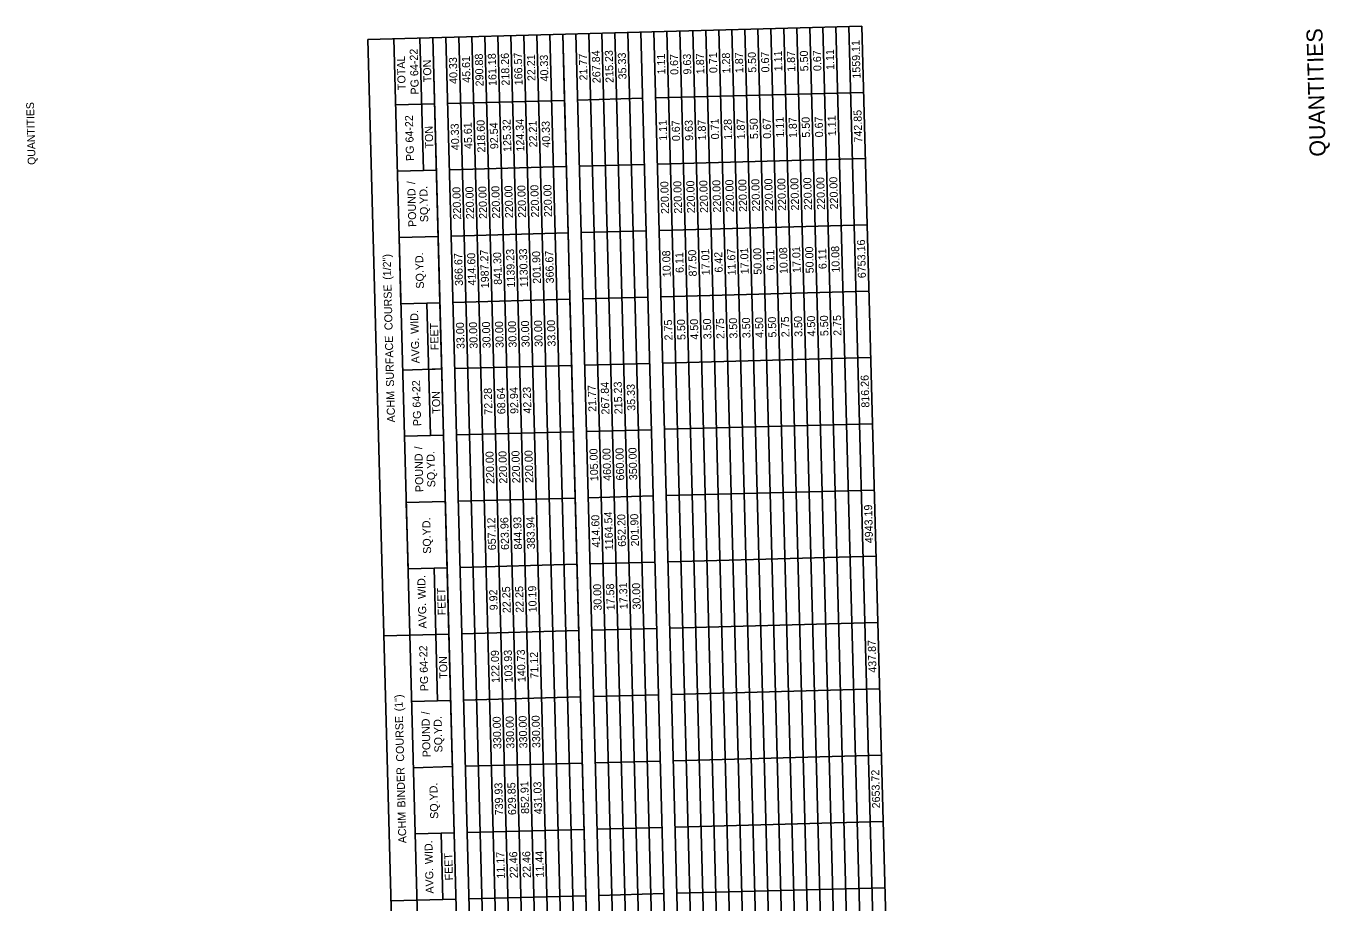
# Model space of a CAD drawing. Extents: x 1930078 to 1931323, y 596452 to 607874.
# Drawn here: x 1930161 to 1931139, y 604738 to 605396 of the extents above; entities that cross this region are included whole.
import ezdxf

# ---------------------------------------------------------------- set-up
doc = ezdxf.new("R2010")
doc.units = 0
for name, color, linetype in [('Default', 7, 'Continuous'), ('R_Border', 7, 'Continuous'), ('R_Border Prem', 7, 'Continuous')]:
    doc.layers.add(name, color=color, linetype=linetype)

msp = doc.modelspace()

# ---------------------------------------------------------------- linework, layer by layer
at = {"layer": 'Default'}
for p, q in [((1930787.82, 605395.91), (1930417.45, 605385.97)), ((1930787.82, 605395.91), (1930417.45, 605385.97)), ((1930564.98, 605340.19), (1930563.65, 605389.9)), ((1930603.34, 603911.35), (1930563.65, 605389.9)), ((1930613.09, 603911.62), (1930573.4, 605390.16)), ((1930622.83, 603911.88), (1930583.14, 605390.42)), ((1930632.58, 603912.14), (1930592.89, 605390.68)), ((1930642.33, 603912.4), (1930602.64, 605390.94)), ((1930652.07, 603912.66), (1930612.38, 605391.21)), ((1930661.82, 603912.92), (1930622.13, 605391.47)), ((1930661.82, 603912.92), (1930622.13, 605391.47)), ((1930671.57, 603913.19), (1930631.88, 605391.73)), ((1930681.31, 603913.45), (1930641.62, 605391.99)), ((1930691.06, 603913.71), (1930651.37, 605392.25)), ((1930700.81, 603913.97), (1930661.12, 605392.51)), ((1930710.55, 603914.23), (1930670.86, 605392.78)), ((1930720.3, 603914.49), (1930680.61, 605393.04)), ((1930730.04, 603914.76), (1930690.35, 605393.3)), ((1930739.79, 603915.02), (1930700.1, 605393.56)), ((1930749.54, 603915.28), (1930709.85, 605393.82)), ((1930759.28, 603915.54), (1930719.59, 605394.08)), ((1930769.03, 603915.8), (1930729.34, 605394.35)), ((1930778.78, 603916.06), (1930739.09, 605394.61)), ((1930788.52, 603916.33), (1930748.83, 605394.87)), ((1930798.27, 603916.59), (1930758.58, 605395.13)), ((1930808.02, 603916.85), (1930768.33, 605395.39)), ((1930817.76, 603917.11), (1930778.07, 605395.65)), ((1930827.51, 603917.37), (1930787.82, 605395.91)), ((1930457.14, 603907.43), (1930417.45, 605385.97)), ((1930466.3, 604292.94), (1930436.95, 605386.5)), ((1930459.11, 605287.61), (1930456.44, 605387.02)), ((1930505.88, 603908.74), (1930466.19, 605387.28)), ((1930471.52, 605188.45), (1930466.19, 605387.28)), ((1930515.62, 603909), (1930475.93, 605387.54)), ((1930525.37, 603909.26), (1930485.68, 605387.8)), ((1930535.12, 603909.52), (1930495.42, 605388.07)), ((1930544.86, 603909.79), (1930505.17, 605388.33)), ((1930554.61, 603910.05), (1930514.92, 605388.59)), ((1930564.35, 603910.31), (1930524.66, 605388.85)), ((1930574.1, 603910.57), (1930534.41, 605389.11)), ((1930583.85, 603910.83), (1930544.16, 605389.37)), ((1930593.59, 603911.09), (1930553.9, 605389.64)), ((1930623.46, 605341.76), (1930574.73, 605340.45)), ((1930623.46, 605341.76), (1930574.73, 605340.45)), ((1930789.15, 605346.21), (1930633.21, 605342.02)), ((1930789.15, 605346.21), (1930633.21, 605342.02)), ((1930467.52, 605337.57), (1930438.28, 605336.79)), ((1930564.98, 605340.19), (1930477.27, 605337.84)), ((1930564.98, 605340.19), (1930477.27, 605337.84)), ((1930567.65, 605240.78), (1930564.98, 605340.19)), ((1930790.49, 605296.5), (1930634.54, 605292.31)), ((1930790.49, 605296.5), (1930634.54, 605292.31)), ((1930468.85, 605287.87), (1930439.61, 605287.08)), ((1930566.32, 605290.48), (1930478.6, 605288.13)), ((1930566.32, 605290.48), (1930478.6, 605288.13)), ((1930624.8, 605292.05), (1930576.07, 605290.74)), ((1930624.8, 605292.05), (1930576.07, 605290.74)), ((1930791.82, 605246.79), (1930635.88, 605242.61)), ((1930791.82, 605246.79), (1930635.88, 605242.61)), ((1930470.19, 605238.16), (1930440.95, 605237.37)), ((1930442.28, 605187.67), (1930440.95, 605237.37)), ((1930567.65, 605240.78), (1930479.93, 605238.42)), ((1930567.65, 605240.78), (1930479.93, 605238.42)), ((1930568.99, 605191.07), (1930567.65, 605240.78)), ((1930626.13, 605242.35), (1930577.4, 605241.04)), ((1930626.13, 605242.35), (1930577.4, 605241.04)), ((1930793.16, 605197.09), (1930637.21, 605192.9)), ((1930793.16, 605197.09), (1930637.21, 605192.9)), ((1930471.52, 605188.45), (1930442.28, 605187.67)), ((1930471.52, 605188.45), (1930461.78, 605188.19)), ((1930464.45, 605088.78), (1930461.78, 605188.19)), ((1930476.86, 604989.62), (1930471.52, 605188.45)), ((1930568.99, 605191.07), (1930481.27, 605188.71)), ((1930568.99, 605191.07), (1930481.27, 605188.71)), ((1930581, 604743.71), (1930568.99, 605191.07)), ((1930627.47, 605192.64), (1930578.73, 605191.33)), ((1930627.47, 605192.64), (1930578.73, 605191.33)), ((1930794.49, 605147.38), (1930638.55, 605143.19)), ((1930794.49, 605147.38), (1930638.55, 605143.19)), ((1930472.86, 605138.75), (1930443.62, 605137.96)), ((1930472.86, 605138.75), (1930463.11, 605138.48)), ((1930570.32, 605141.36), (1930482.6, 605139.01)), ((1930570.32, 605141.36), (1930482.6, 605139.01)), ((1930628.8, 605142.93), (1930580.07, 605141.62)), ((1930628.8, 605142.93), (1930580.07, 605141.62)), ((1930795.83, 605097.67), (1930639.88, 605093.49)), ((1930795.83, 605097.67), (1930639.88, 605093.49)), ((1930474.19, 605089.04), (1930444.95, 605088.25)), ((1930571.66, 605091.65), (1930483.94, 605089.3)), ((1930571.66, 605091.65), (1930483.94, 605089.3)), ((1930630.14, 605093.22), (1930581.4, 605091.92)), ((1930630.14, 605093.22), (1930581.4, 605091.92)), ((1930797.16, 605047.97), (1930641.22, 605043.78)), ((1930797.16, 605047.97), (1930641.22, 605043.78)), ((1930475.53, 605039.33), (1930446.29, 605038.55)), ((1930447.62, 604988.84), (1930446.29, 605038.55)), ((1930572.99, 605041.95), (1930485.27, 605039.59)), ((1930572.99, 605041.95), (1930485.27, 605039.59)), ((1930631.47, 605043.52), (1930582.74, 605042.21)), ((1930631.47, 605043.52), (1930582.74, 605042.21)), ((1930476.86, 604989.62), (1930447.62, 604988.84)), ((1930476.86, 604989.62), (1930467.11, 604989.36)), ((1930469.78, 604889.95), (1930467.11, 604989.36)), ((1930482.2, 604790.8), (1930476.86, 604989.62)), ((1930574.33, 604992.24), (1930486.61, 604989.89)), ((1930574.33, 604992.24), (1930486.61, 604989.89)), ((1930632.8, 604993.81), (1930584.07, 604992.5)), ((1930632.8, 604993.81), (1930584.07, 604992.5)), ((1930798.49, 604998.26), (1930642.55, 604994.07)), ((1930798.49, 604998.26), (1930642.55, 604994.07)), ((1930575.66, 604942.53), (1930487.94, 604940.18)), ((1930575.66, 604942.53), (1930487.94, 604940.18)), ((1930634.14, 604944.1), (1930585.41, 604942.8)), ((1930634.14, 604944.1), (1930585.41, 604942.8)), ((1930799.83, 604948.55), (1930643.88, 604944.36)), ((1930799.83, 604948.55), (1930643.88, 604944.36)), ((1930478.19, 604939.92), (1930429.46, 604938.61)), ((1930448.96, 604939.13), (1930429.46, 604938.61)), ((1930478.19, 604939.92), (1930468.45, 604939.66)), ((1930576.99, 604892.83), (1930489.28, 604890.47)), ((1930576.99, 604892.83), (1930489.28, 604890.47)), ((1930635.47, 604894.4), (1930586.74, 604893.09)), ((1930635.47, 604894.4), (1930586.74, 604893.09)), ((1930801.16, 604898.84), (1930645.22, 604894.66)), ((1930801.16, 604898.84), (1930645.22, 604894.66)), ((1930479.53, 604890.21), (1930450.29, 604889.43)), ((1930578.33, 604843.12), (1930490.61, 604840.76)), ((1930578.33, 604843.12), (1930490.61, 604840.76)), ((1930636.81, 604844.69), (1930588.07, 604843.38)), ((1930636.81, 604844.69), (1930588.07, 604843.38)), ((1930802.5, 604849.14), (1930646.55, 604844.95)), ((1930802.5, 604849.14), (1930646.55, 604844.95)), ((1930480.86, 604840.5), (1930451.62, 604839.72)), ((1930638.14, 604794.98), (1930589.41, 604793.67)), ((1930638.14, 604794.98), (1930589.41, 604793.67)), ((1930803.83, 604799.43), (1930647.89, 604795.24)), ((1930803.83, 604799.43), (1930647.89, 604795.24)), ((1930482.2, 604790.8), (1930452.96, 604790.01)), ((1930482.2, 604790.8), (1930472.45, 604790.53)), ((1930473.79, 604740.83), (1930472.45, 604790.53)), ((1930486.2, 604641.67), (1930482.2, 604790.8)), ((1930579.66, 604793.41), (1930491.94, 604791.06)), ((1930579.66, 604793.41), (1930491.94, 604791.06)), ((1930639.48, 604745.27), (1930590.74, 604743.97)), ((1930639.48, 604745.27), (1930590.74, 604743.97)), ((1930805.17, 604749.72), (1930649.22, 604745.54)), ((1930805.17, 604749.72), (1930649.22, 604745.54)), ((1930483.53, 604741.09), (1930434.8, 604739.78)), ((1930581, 604743.71), (1930493.28, 604741.35)), ((1930581, 604743.71), (1930493.28, 604741.35)), ((1930585, 604594.58), (1930581, 604743.71))]:
    msp.add_line(p, q, dxfattribs=at)

# ---------------------------------------------------------------- texts
for s, p in [('1559.11', (1930787, 605356.55)), ('TOTAL', (1930445.86, 605348.01)), (' 64-22', (1930455.39, 605356.25)), ('40.33', (1930484.75, 605352.61)), ('45.61', (1930494.48, 605353.45)), ('290.88', (1930504.3, 605350.8)), ('161.18', (1930514.05, 605351.06)), ('218.26', (1930523.8, 605351.33)), ('166.57', (1930533.54, 605351.59)), ('22.21', (1930543.21, 605354.76)), ('40.33', (1930552.97, 605354.44)), ('21.77', (1930582.21, 605355.23)), ('267.84', (1930592.02, 605353.17)), ('215.23', (1930601.77, 605353.42)), ('35.33', (1930611.45, 605356.01)), ('1.11', (1930640.61, 605359.71)), ('0.67', (1930650.38, 605359.39)), ('9.63', (1930660.12, 605359.65)), ('1.87', (1930669.87, 605359.91)), ('0.71', (1930679.6, 605360.75)), ('1.28', (1930689.36, 605360.43)), ('1.87', (1930699.11, 605360.7)), ('5.50', (1930708.85, 605360.97)), ('0.67', (1930718.6, 605361.22)), ('1.11', (1930728.33, 605362.06)), ('1.87', (1930738.09, 605361.74)), ('5.50', (1930747.84, 605362.01)), ('0.67', (1930757.59, 605362.26)), ('1.11', (1930767.32, 605363.11)), ('TON', (1930465.21, 605353.87)), ('PG', (1930455.7, 605344.65)), ('742.85', (1930788.29, 605308.62)), (' 64-22', (1930451.85, 605306.41)), ('40.33', (1930486.08, 605302.9)), ('45.61', (1930495.81, 605303.75)), ('218.60', (1930505.64, 605301.11)), ('92.54', (1930515.32, 605303.7)), ('125.32', (1930525.13, 605301.65)), ('124.34', (1930534.88, 605301.9)), ('22.21', (1930544.55, 605305.05)), ('40.33', (1930554.31, 605304.73)), ('1.11', (1930641.95, 605310)), ('0.67', (1930651.71, 605309.68)), ('9.63', (1930661.46, 605309.94)), ('1.87', (1930671.2, 605310.2)), ('0.71', (1930680.93, 605311.05)), ('1.28', (1930690.7, 605310.72)), ('1.87', (1930700.44, 605310.99)), ('5.50', (1930710.19, 605311.26)), ('0.67', (1930719.94, 605311.51)), ('1.11', (1930729.67, 605312.35)), ('1.87', (1930739.43, 605312.03)), ('5.50', (1930749.17, 605312.31)), ('0.67', (1930758.92, 605312.56)), ('1.11', (1930768.65, 605313.4)), ('TON', (1930466.54, 605304.16)), ('PG', (1930452.16, 605294.81)), ('220.00', (1930760.38, 605258.2)), ('220.00', (1930770.13, 605258.47)), (' /', (1930453.06, 605275.18)), ('POUND', (1930453.87, 605245.32)), ('SQ.YD.', (1930462.77, 605248.91)), ('220.00', (1930487.48, 605250.88)), ('220.00', (1930497.22, 605251.14)), ('220.00', (1930506.97, 605251.4)), ('220.00', (1930516.72, 605251.66)), ('220.00', (1930526.46, 605251.92)), ('220.00', (1930536.21, 605252.19)), ('220.00', (1930545.96, 605252.45)), ('220.00', (1930555.7, 605252.71)), ('220.00', (1930643.42, 605255.06)), ('220.00', (1930653.17, 605255.33)), ('220.00', (1930662.92, 605255.59)), ('220.00', (1930672.66, 605255.85)), ('220.00', (1930682.41, 605256.11)), ('220.00', (1930692.15, 605256.37)), ('220.00', (1930701.9, 605256.63)), ('220.00', (1930711.65, 605256.9)), ('220.00', (1930721.39, 605257.16)), ('220.00', (1930731.14, 605257.42)), ('220.00', (1930740.89, 605257.68)), ('220.00', (1930750.63, 605257.94)), ('6753.16', (1930791.02, 605206.9)), (' (1/2")', (1930435.11, 605203.46)), ('SQ.YD.', (1930459.61, 605199.08)), ('366.67', (1930488.81, 605201.16)), ('414.60', (1930498.56, 605201.43)), ('1987.27', (1930508.37, 605199.35)), ('841.30', (1930518.05, 605201.96)), ('1139.23', (1930527.86, 605199.88)), ('1130.33', (1930537.61, 605200.14)), ('201.90', (1930547.29, 605202.74)), ('366.67', (1930557.04, 605202.99)), ('10.08', (1930644.69, 605207.67)), ('6.11', (1930654.36, 605210.85)), ('87.50', (1930664.19, 605208.21)), ('17.01', (1930673.92, 605209.04)), ('6.42', (1930683.62, 605211.08)), ('11.67', (1930693.43, 605208.98)), ('17.01', (1930703.16, 605209.83)), ('50.00', (1930712.92, 605209.52)), ('6.11', (1930722.59, 605212.68)), ('10.08', (1930732.41, 605210.02)), ('17.01', (1930742.14, 605210.87)), ('50.00', (1930751.91, 605210.56)), ('6.11', (1930761.57, 605213.72)), ('10.08', (1930771.4, 605211.07)), (' COURSE', (1930436.12, 605165.69)), (' WID.', (1930455.7, 605162.93)), ('30.00', (1930538.82, 605155.1)), ('30.00', (1930548.56, 605155.36)), ('33.00', (1930558.31, 605155.62)), ('2.75', (1930645.97, 605160.27)), ('5.50', (1930655.71, 605160.57)), ('4.50', (1930665.46, 605160.83)), ('3.50', (1930675.21, 605161.09)), ('2.75', (1930684.95, 605161.32)), ('3.50', (1930694.7, 605161.62)), ('3.50', (1930704.44, 605161.88)), ('4.50', (1930714.19, 605162.14)), ('5.50', (1930723.94, 605162.4)), ('2.75', (1930733.69, 605162.63)), ('3.50', (1930743.43, 605162.92)), ('4.50', (1930753.18, 605163.19)), ('5.50', (1930762.92, 605163.45)), ('2.75', (1930772.67, 605163.68)), ('FEET', (1930470.6, 605152.92)), ('33.00', (1930490.08, 605153.79)), ('30.00', (1930499.83, 605154.05)), ('30.00', (1930509.58, 605154.32)), ('30.00', (1930519.32, 605154.58)), ('30.00', (1930529.07, 605154.84)), (' SURFACE', (1930437.26, 605123.26)), ('AVG.', (1930456.24, 605143.02)), (' 64-22', (1930457.19, 605107.59)), ('21.77', (1930588.88, 605106.69)), ('267.84', (1930598.69, 605104.64)), ('215.23', (1930608.44, 605104.88)), ('35.33', (1930618.12, 605107.48)), ('816.26', (1930793.62, 605109.81)), ('ACHM', (1930437.92, 605098.72)), ('TON', (1930471.88, 605105.33)), ('72.28', (1930510.91, 605104.59)), ('68.64', (1930520.66, 605104.87)), ('92.94', (1930530.4, 605105.13)), ('42.23', (1930540.15, 605105.38)), ('PG', (1930457.5, 605095.98)), (' /', (1930458.4, 605076.35)), ('220.00', (1930522.06, 605052.83)), ('220.00', (1930531.8, 605053.1)), ('220.00', (1930541.55, 605053.36)), ('105.00', (1930590.28, 605054.67)), ('460.00', (1930600.03, 605054.93)), ('660.00', (1930609.77, 605055.19)), ('350.00', (1930619.52, 605055.45)), ('POUND', (1930459.2, 605046.49)), ('SQ.YD.', (1930468.11, 605050.08)), ('220.00', (1930512.31, 605052.57)), ('414.60', (1930591.62, 605004.96)), ('1164.54', (1930601.42, 605002.89)), ('652.20', (1930611.11, 605005.48)), ('201.90', (1930620.85, 605005.74)), ('4943.19', (1930796.35, 605008.12)), ('SQ.YD.', (1930464.95, 605000.25)), ('657.12', (1930513.64, 605002.89)), ('623.96', (1930523.39, 605003.12)), ('844.93', (1930533.14, 605003.38)), ('383.94', (1930542.88, 605003.65)), (' WID.', (1930461.04, 604964.1)), ('FEET', (1930475.94, 604954.1)), ('9.92', (1930514.85, 604957.84)), ('22.25', (1930524.66, 604955.72)), ('22.25', (1930534.41, 604955.98)), ('10.19', (1930544.15, 604956.26)), ('30.00', (1930592.89, 604957.58)), ('17.58', (1930602.63, 604957.83)), ('17.31', (1930612.36, 604958.67)), ('30.00', (1930622.13, 604958.37)), ('AVG.', (1930461.57, 604944.19)), (' 64-22', (1930462.53, 604908.76)), ('437.87', (1930798.96, 604911.02)), ('TON', (1930477.22, 604906.5)), ('122.09', (1930516.31, 604903.44)), ('103.93', (1930526.06, 604903.7)), ('140.73', (1930535.81, 604903.96)), ('71.12', (1930545.49, 604906.59)), ('PG', (1930462.84, 604897.16)), (' (1")', (1930443.79, 604879.85)), (' /', (1930463.74, 604877.52)), (' COURSE', (1930444.81, 604842.08)), ('POUND', (1930464.54, 604847.67)), ('SQ.YD.', (1930473.45, 604851.25)), ('330.00', (1930517.65, 604853.74)), ('330.00', (1930527.39, 604854.01)), ('330.00', (1930537.14, 604854.27)), ('330.00', (1930546.89, 604854.53)), (' BINDER', (1930445.73, 604807.66)), ('2653.72', (1930801.69, 604809.3)), ('SQ.YD.', (1930470.28, 604801.42)), ('739.93', (1930518.98, 604804.03)), ('629.85', (1930528.73, 604804.26)), ('852.91', (1930538.46, 604805.13)), ('431.03', (1930548.22, 604804.81)), ('ACHM', (1930446.39, 604783.12)), (' WID.', (1930466.38, 604765.27)), ('FEET', (1930481.28, 604755.27)), ('11.17', (1930520.25, 604756.65)), ('22.46', (1930530, 604756.91)), ('22.46', (1930539.75, 604757.17)), ('11.44', (1930549.49, 604757.45)), ('AVG.', (1930466.91, 604745.36))]:
    msp.add_text(s, height=6, rotation=91.53769, dxfattribs=at).set_placement(p)
at = {"layer": 'R_Border'}
msp.add_text('QUANTITIES', height=12, rotation=91.53769, dxfattribs=at).set_placement((1931135.88, 605298.16))
at = {"layer": 'R_Border Prem'}
msp.add_text('QUANTITIES', height=5.862, rotation=91.53769, dxfattribs=at).set_placement((1930168.33, 605291.91))

doc.saveas('drawing.dxf')
